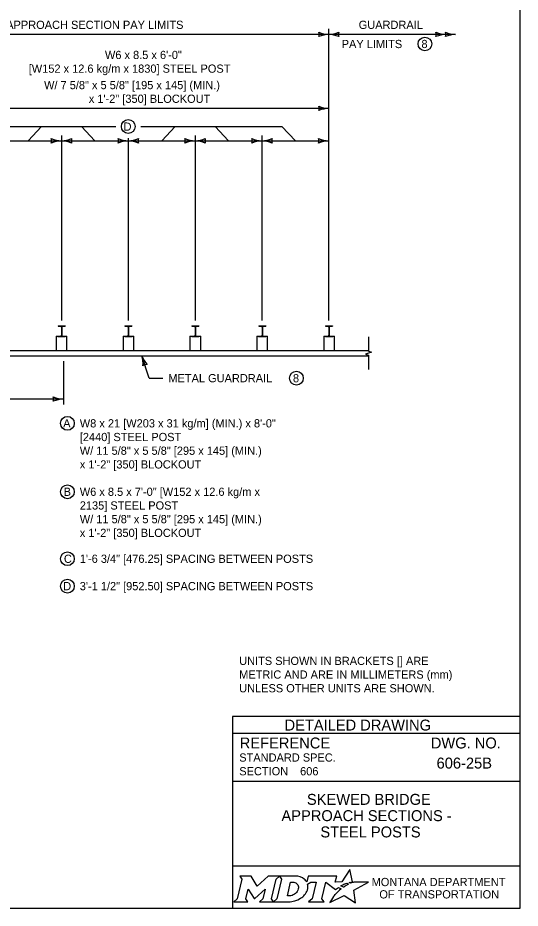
# Model space of a CAD drawing. Extents: x 49991.4 to 50021, y 49987.6 to 50011.4.
# Drawn here: x 50004.95 to 50008.61, y 50000.06 to 50006.57 of the extents above; entities that cross this region are included whole.
import ezdxf

# ---------------------------------------------------------------- set-up
doc = ezdxf.new("R2010")
doc.units = 0
for name, color, linetype in [('Level 1', 7, 'Continuous'), ('Level 2', 7, 'Continuous'), ('Level 3', 7, 'Continuous'), ('Level 6', 7, 'Continuous')]:
    doc.layers.add(name, color=color, linetype=linetype)

msp = doc.modelspace()

# ---------------------------------------------------------------- linework, layer by layer
at = {"layer": 'Level 1'}
for p, q in [((50005.2428, 50004.3152), (50005.294, 50004.3152)), ((50005.2428, 50004.3152), (50005.2428, 50004.3124)), ((50005.2428, 50004.3124), (50005.2603, 50004.3124)), ((50005.2673, 50004.3054), (50005.2673, 50004.2469)), ((50005.2695, 50004.3054), (50005.2695, 50004.2469)), ((50005.2765, 50004.3124), (50005.294, 50004.3124)), ((50005.294, 50004.3152), (50005.294, 50004.3124)), ((50005.7307, 50004.3152), (50005.782, 50004.3152)), ((50005.7307, 50004.3152), (50005.7307, 50004.3124)), ((50005.7307, 50004.3124), (50005.7483, 50004.3124)), ((50005.7552, 50004.3054), (50005.7552, 50004.2469)), ((50005.7574, 50004.3054), (50005.7574, 50004.2469)), ((50005.7644, 50004.3124), (50005.782, 50004.3124)), ((50005.782, 50004.3152), (50005.782, 50004.3124)), ((50006.2187, 50004.3152), (50006.2699, 50004.3152)), ((50006.2187, 50004.3152), (50006.2187, 50004.3124)), ((50006.2187, 50004.3124), (50006.2362, 50004.3124)), ((50006.2432, 50004.3054), (50006.2432, 50004.2469)), ((50006.2454, 50004.3054), (50006.2454, 50004.2469)), ((50006.2524, 50004.3124), (50006.2699, 50004.3124)), ((50006.2699, 50004.3152), (50006.2699, 50004.3124)), ((50006.7066, 50004.3152), (50006.7579, 50004.3152)), ((50006.7066, 50004.3152), (50006.7066, 50004.3124)), ((50006.7066, 50004.3124), (50006.7242, 50004.3124)), ((50006.7311, 50004.3054), (50006.7311, 50004.2469)), ((50006.7333, 50004.3054), (50006.7333, 50004.2469)), ((50006.7403, 50004.3124), (50006.7579, 50004.3124)), ((50006.7579, 50004.3152), (50006.7579, 50004.3124)), ((50007.1945, 50004.3152), (50007.2458, 50004.3152)), ((50007.1945, 50004.3152), (50007.1945, 50004.3124)), ((50007.1945, 50004.3124), (50007.2121, 50004.3124)), ((50007.2191, 50004.3054), (50007.2191, 50004.2469)), ((50007.2213, 50004.3054), (50007.2213, 50004.2469)), ((50007.2282, 50004.3124), (50007.2458, 50004.3124)), ((50007.2458, 50004.3152), (50007.2458, 50004.3124)), ((50005.2294, 50004.2399), (50005.2294, 50004.1359)), ((50005.2294, 50004.2399), (50005.2421, 50004.2399)), ((50005.2421, 50004.2371), (50005.2421, 50004.2399)), ((50005.2421, 50004.2371), (50005.2947, 50004.2371)), ((50005.2428, 50004.2371), (50005.2428, 50004.2399)), ((50005.2428, 50004.2399), (50005.2603, 50004.2399)), ((50005.2765, 50004.2399), (50005.294, 50004.2399)), ((50005.294, 50004.2371), (50005.294, 50004.2399)), ((50005.2947, 50004.2371), (50005.2947, 50004.2399)), ((50005.2947, 50004.2399), (50005.3074, 50004.2399)), ((50005.3074, 50004.1359), (50005.3074, 50004.2399)), ((50005.7173, 50004.2403), (50005.7173, 50004.1359)), ((50005.7173, 50004.2399), (50005.7301, 50004.2399)), ((50005.7301, 50004.2371), (50005.7301, 50004.2399)), ((50005.7301, 50004.2371), (50005.7826, 50004.2371)), ((50005.7307, 50004.2371), (50005.7307, 50004.2399)), ((50005.7307, 50004.2399), (50005.7483, 50004.2399)), ((50005.7644, 50004.2399), (50005.782, 50004.2399)), ((50005.782, 50004.2371), (50005.782, 50004.2399)), ((50005.7826, 50004.2371), (50005.7826, 50004.2399)), ((50005.7826, 50004.2399), (50005.7954, 50004.2399)), ((50005.7954, 50004.1359), (50005.7954, 50004.2399)), ((50006.2053, 50004.2399), (50006.2053, 50004.1359)), ((50006.2053, 50004.2399), (50006.218, 50004.2399)), ((50006.218, 50004.2371), (50006.218, 50004.2399)), ((50006.218, 50004.2371), (50006.2706, 50004.2371)), ((50006.2187, 50004.2371), (50006.2187, 50004.2399)), ((50006.2187, 50004.2399), (50006.2362, 50004.2399)), ((50006.2524, 50004.2399), (50006.2699, 50004.2399)), ((50006.2699, 50004.2371), (50006.2699, 50004.2399)), ((50006.2706, 50004.2371), (50006.2706, 50004.2399)), ((50006.2706, 50004.2399), (50006.2833, 50004.2399)), ((50006.2833, 50004.1359), (50006.2833, 50004.2399)), ((50006.6932, 50004.2399), (50006.6932, 50004.1359)), ((50006.6932, 50004.2399), (50006.7059, 50004.2399)), ((50006.7059, 50004.2371), (50006.7059, 50004.2399)), ((50006.7059, 50004.2371), (50006.7585, 50004.2371)), ((50006.7066, 50004.2371), (50006.7066, 50004.2399)), ((50006.7066, 50004.2399), (50006.7242, 50004.2399)), ((50006.7403, 50004.2399), (50006.7579, 50004.2399)), ((50006.7579, 50004.2371), (50006.7579, 50004.2399)), ((50006.7585, 50004.2371), (50006.7585, 50004.2399)), ((50006.7585, 50004.2399), (50006.7713, 50004.2399)), ((50006.7713, 50004.1359), (50006.7713, 50004.2399)), ((50007.1811, 50004.2399), (50007.1811, 50004.1359)), ((50007.1811, 50004.2399), (50007.1939, 50004.2399)), ((50007.1939, 50004.2371), (50007.1939, 50004.2399)), ((50007.1939, 50004.2371), (50007.2465, 50004.2371)), ((50007.1945, 50004.2371), (50007.1945, 50004.2399)), ((50007.1945, 50004.2399), (50007.2121, 50004.2399)), ((50007.2282, 50004.2399), (50007.2458, 50004.2399)), ((50007.2458, 50004.2371), (50007.2458, 50004.2399)), ((50007.2465, 50004.2371), (50007.2465, 50004.2399)), ((50007.2465, 50004.2399), (50007.2592, 50004.2399)), ((50007.2592, 50004.1359), (50007.2592, 50004.2399)), ((50003.0353, 50004.1359), (50007.507, 50004.1359)), ((50001.9767, 50004.0968), (50007.507, 50004.0968))]:
    msp.add_line(p, q, dxfattribs=at)
msp.add_lwpolyline([(50008.6146, 50011.2628), (50000.3356, 50011.2628), (50000.3356, 50000.0624), (50008.6146, 50000.0624)], close=True, dxfattribs=at)
for centre, start, end in [((50005.2603, 50004.3054), 0, 90), ((50005.2765, 50004.3054), 90, 180), ((50005.7483, 50004.3054), 0, 90), ((50005.7644, 50004.3054), 90, 180), ((50006.2362, 50004.3054), 0, 90), ((50006.2524, 50004.3054), 90, 180), ((50006.7242, 50004.3054), 0, 90), ((50006.7403, 50004.3054), 90, 180), ((50007.2121, 50004.3054), 0, 90), ((50007.2282, 50004.3054), 90, 180), ((50005.2603, 50004.2469), 270, 0), ((50005.2765, 50004.2469), 180, 270), ((50005.7483, 50004.2469), 270, 0), ((50005.7644, 50004.2469), 180, 270), ((50006.2362, 50004.2469), 270, 0), ((50006.2524, 50004.2469), 180, 270), ((50006.7242, 50004.2469), 270, 0), ((50006.7403, 50004.2469), 180, 270), ((50007.2121, 50004.2469), 270, 0), ((50007.2282, 50004.2469), 180, 270)]:
    msp.add_arc(centre, 0.00696, start, end, dxfattribs=at)
at = {"layer": 'Level 2'}
for p, q in [((50008.6146, 50001.4624), (50006.5146, 50001.4624)), ((50006.5146, 50001.4624), (50006.5146, 50000.0624)), ((50008.6146, 50001.3374), (50006.5146, 50001.3374)), ((50008.2507, 50001.1223), (50008.2507, 50001.1223)), ((50007.0089, 50001.0629), (50007.0089, 50001.0629)), ((50008.6146, 50000.9874), (50006.5146, 50000.9874)), ((50007.5646, 50000.7383), (50007.5646, 50000.7383)), ((50008.6146, 50000.3693), (50006.5146, 50000.3693))]:
    msp.add_line(p, q, dxfattribs=at)
for points in [[(50006.5701, 50000.2974), (50006.5842, 50000.274), (50006.5507, 50000.1307), (50006.525, 50000.1082), (50006.6266, 50000.1082), (50006.6131, 50000.131), (50006.6293, 50000.2011), (50006.673, 50000.1321), (50006.6783, 50000.1321), (50006.7534, 50000.2016), (50006.737, 50000.1305), (50006.7123, 50000.1085), (50006.8139, 50000.1085), (50006.8001, 50000.1318), (50006.8333, 50000.2742)], [(50006.8333, 50000.2742), (50006.8586, 50000.2974), (50006.7762, 50000.2974), (50006.6966, 50000.2244), (50006.6521, 50000.2971), (50006.5701, 50000.2974)], [(50006.9722, 50000.2974), (50006.8586, 50000.2974), (50006.8733, 50000.2745), (50006.8394, 50000.1307), (50006.8139, 50000.1085), (50006.9245, 50000.1085)], [(50007.3771, 50000.2447), (50007.3668, 50000.2503), (50007.3784, 50000.2531), (50007.39, 50000.2551), (50007.3726, 50000.3452), (50007.3131, 50000.2539), (50007.2658, 50000.2532), (50007.2761, 50000.2973), (50007.0669, 50000.2974), (50007.0568, 50000.2549), (50007.051, 50000.2632)], [(50006.9962, 50000.2107), (50006.995, 50000.2026), (50006.9918, 50000.1933), (50006.9876, 50000.1851), (50006.982, 50000.1776), (50006.9755, 50000.1707), (50006.9676, 50000.1644), (50006.9593, 50000.1597), (50006.9502, 50000.1558), (50006.9411, 50000.1535), (50006.9319, 50000.1526), (50006.916, 50000.1526), (50006.9396, 50000.2526), (50006.9556, 50000.2526), (50006.9632, 50000.252), (50006.9708, 50000.2501), (50006.9774, 50000.2471), (50006.9835, 50000.2429), (50006.9883, 50000.2379), (50006.992, 50000.2319), (50006.9947, 50000.2257), (50006.9963, 50000.2183), (50006.9963, 50000.2153), (50006.9962, 50000.2107)], [(50007.0636, 50000.2383), (50007.0882, 50000.2514), (50007.1251, 50000.2514), (50007.0965, 50000.1309), (50007.069, 50000.1082), (50007.1852, 50000.1082), (50007.1682, 50000.1311), (50007.1964, 50000.2513), (50007.2677, 50000.1996), (50007.2888, 50000.2147), (50007.3085, 50000.2038)], [(50007.2527, 50000.1479), (50007.2374, 50000.1235), (50007.2327, 50000.116), (50007.2269, 50000.1074), (50007.2246, 50000.1031), (50007.3299, 50000.1562), (50007.4138, 50000.1011), (50007.4007, 50000.1938), (50007.5076, 50000.2522), (50007.4583, 50000.253), (50007.4282, 50000.2534), (50007.4074, 50000.2537), (50007.4006, 50000.2522), (50007.3957, 50000.251), (50007.3873, 50000.2487), (50007.3771, 50000.2447)], [(50007.3267, 50000.2171), (50007.3243, 50000.2154), (50007.306, 50000.225), (50007.3163, 50000.2307), (50007.3204, 50000.2329), (50007.329, 50000.2369), (50007.3347, 50000.2395), (50007.3426, 50000.2425), (50007.3499, 50000.2452), (50007.3617, 50000.2378), (50007.3577, 50000.2357), (50007.3531, 50000.2332), (50007.3489, 50000.231), (50007.3439, 50000.2281), (50007.342, 50000.227), (50007.3393, 50000.2254), (50007.3368, 50000.224), (50007.3345, 50000.2224), (50007.3319, 50000.2206), (50007.3292, 50000.2188), (50007.3267, 50000.2171)], [(50006.9702, 50000.1158), (50006.9786, 50000.1184), (50006.9916, 50000.1238), (50007.012, 50000.1348)], [(50007.2666, 50000.164), (50007.2666, 50000.164)]]:
    msp.add_lwpolyline(points, dxfattribs=at)
for centre, radius in [((50007.9192, 50006.3745), 0.05), ((50005.755, 50005.7717), 0.0505), ((50006.9816, 50003.9337), 0.05), ((50005.3109, 50003.6039), 0.0504), ((50005.3109, 50003.1039), 0.0504), ((50005.3108, 50002.6147), 0.0504), ((50005.3108, 50002.4147), 0.0505)]:
    msp.add_circle(centre, radius, dxfattribs=at)
for centre, radius, start, end in [((50006.9953, 50000.219), 0.0709, 339.53292, 15.85821), ((50006.9513, 50000.2363), 0.1183, 300.91025, 339.13831)]:
    msp.add_arc(centre, radius, start, end, dxfattribs=at)
for centre, major_axis, ratio, start_param, end_param in [((50006.9701, 50000.25), (0.0834, -0.0037), 0.568097, 0.61298, 1.570796), ((50007.0257, 50000.2573), (0.0361, -0.0295), 0.469099, 1.225588, 1.570796), ((50007.2764, 50000.1742), (-0.0098, -0.0102), 0.016458, 3.141593, 6.279097), ((50007.2974, 50000.1941), (-0.0112, -0.0097), 0.021651, 3.157348, 6.283185), ((50006.9248, 50000.2568), (0, 0.1484), 0.987302, 3.139398, 3.456847), ((50007.2597, 50000.1559), (-0.00694, -0.00806), 0.008222, 0, 3.137361)]:
    msp.add_ellipse(centre, major_axis=major_axis, ratio=ratio, start_param=start_param, end_param=end_param, dxfattribs=at)
at = {"layer": 'Level 3'}
for p, q in [((50007.2182, 50004.3552), (50007.2182, 50006.4845)), ((50007.2182, 50006.4445), (50003.3166, 50006.4445)), ((50008.1422, 50006.4445), (50007.2182, 50006.4445)), ((50004.7798, 50005.9046), (50007.2182, 50005.9046)), ((50004.634, 50005.7717), (50005.6646, 50005.7717)), ((50005.1218, 50005.7717), (50005.0235, 50005.6672)), ((50005.4129, 50005.7717), (50005.5112, 50005.6672)), ((50005.8455, 50005.7717), (50006.8761, 50005.7717)), ((50006.0971, 50005.7717), (50005.9989, 50005.6672)), ((50006.3883, 50005.7717), (50006.4866, 50005.6672)), ((50006.8761, 50005.7717), (50006.9743, 50005.6672)), ((50005.2673, 50005.7072), (50005.2673, 50004.3552)), ((50006.2427, 50005.7072), (50006.2427, 50004.3552)), ((50006.7304, 50005.7072), (50006.7304, 50004.3552)), ((50004.7797, 50005.6672), (50005.2673, 50005.6672)), ((50005.2673, 50005.6672), (50005.755, 50005.6672)), ((50005.755, 50005.6878), (50005.755, 50004.3552)), ((50005.755, 50005.6672), (50006.2427, 50005.6672)), ((50006.2427, 50005.6672), (50006.7304, 50005.6672)), ((50006.7304, 50005.6672), (50007.2182, 50005.6672)), ((50005.9078, 50003.9337), (50005.8547, 50004.0968)), ((50005.2821, 50004.0568), (50005.2821, 50003.7411)), ((50005.9078, 50003.9337), (50006.0076, 50003.9337)), ((50005.2821, 50003.7811), (50003.3313, 50003.7811)), ((50005.2821, 50003.7811), (50005.2821, 50003.7811))]:
    msp.add_line(p, q, dxfattribs=at)
for centre, radius, start, end in [((50007.2269, 50006.6556), 0.2113, 247.45601, 267.63952), ((50007.0964, 50006.4445), 0.0521, 342.13882, 17.86118), ((50007.2291, 50006.2234), 0.2214, 92.82731, 112.07716), ((50007.2073, 50006.6657), 0.2214, 272.82731, 292.07716), ((50007.2095, 50006.2334), 0.2113, 67.45601, 87.63952), ((50007.34, 50006.4445), 0.0521, 162.13882, 197.86118), ((50008.0811, 50006.6556), 0.2113, 247.45601, 267.63952), ((50007.9506, 50006.4445), 0.0521, 342.13882, 17.86118), ((50008.0834, 50006.2234), 0.2214, 92.82731, 112.07716), ((50008.1509, 50006.6556), 0.2113, 247.45601, 267.63952), ((50008.0204, 50006.4445), 0.0521, 342.13882, 17.86118), ((50008.1531, 50006.2234), 0.2214, 92.82731, 112.07716), ((50007.2269, 50006.1157), 0.2113, 247.45601, 267.63952), ((50007.0964, 50005.9046), 0.0521, 342.13882, 17.86118), ((50007.2291, 50005.6834), 0.2214, 92.82731, 112.07716), ((50005.2763, 50005.8839), 0.2168, 247.45601, 267.63952), ((50005.1423, 50005.6672), 0.0534, 342.13882, 17.86118), ((50005.2786, 50005.4403), 0.2273, 92.82731, 112.07716), ((50005.2561, 50005.8942), 0.2273, 272.82731, 292.07716), ((50005.2584, 50005.4506), 0.2168, 67.45601, 87.63952), ((50005.3924, 50005.6672), 0.0534, 162.13882, 197.86118), ((50005.764, 50005.8839), 0.2168, 247.45601, 267.63952), ((50005.63, 50005.6672), 0.0534, 342.13882, 17.86118), ((50005.7662, 50005.4403), 0.2273, 92.82731, 112.07716), ((50005.7438, 50005.8942), 0.2273, 272.82731, 292.07716), ((50005.7461, 50005.4506), 0.2168, 67.45601, 87.63952), ((50005.8801, 50005.6672), 0.0534, 162.13882, 197.86118), ((50006.2516, 50005.8839), 0.2168, 247.45601, 267.63952), ((50006.1177, 50005.6672), 0.0534, 342.13882, 17.86118), ((50006.2539, 50005.4403), 0.2273, 92.82731, 112.07716), ((50006.2315, 50005.8942), 0.2273, 272.82731, 292.07716), ((50006.2338, 50005.4506), 0.2168, 67.45601, 87.63952), ((50006.3678, 50005.6672), 0.0534, 162.13882, 197.86118), ((50006.7393, 50005.8839), 0.2168, 247.45601, 267.63952), ((50006.6053, 50005.6672), 0.0534, 342.13882, 17.86118), ((50006.7416, 50005.4403), 0.2273, 92.82731, 112.07716), ((50006.7192, 50005.8942), 0.2273, 272.82731, 292.07716), ((50006.7215, 50005.4506), 0.2168, 67.45601, 87.63952), ((50006.8555, 50005.6672), 0.0534, 162.13882, 197.86118), ((50007.2271, 50005.8839), 0.2168, 247.45601, 267.63952), ((50007.0931, 50005.6672), 0.0534, 342.13882, 17.86118), ((50007.2294, 50005.4403), 0.2273, 92.82731, 112.07716), ((50005.6513, 50004.0398), 0.2113, 355.47646, 15.65997), ((50006.0616, 50004.1756), 0.2214, 200.84776, 220.09761), ((50005.8924, 50003.981), 0.0521, 90.15927, 125.88163), ((50005.291, 50003.9978), 0.2168, 247.45601, 267.63952), ((50005.157, 50003.7811), 0.0534, 342.13882, 17.86118), ((50005.2933, 50003.5541), 0.2273, 92.82731, 112.07716)]:
    msp.add_arc(centre, radius, start, end, dxfattribs=at)
at = {"layer": 'Level 6'}
for p, q in [((50007.507, 50004.2359), (50007.507, 50004.1317)), ((50007.5286, 50004.124), (50007.4853, 50004.1086)), ((50007.4853, 50004.1086), (50007.507, 50004.1009)), ((50007.507, 50004.1317), (50007.5286, 50004.124)), ((50007.507, 50004.1009), (50007.507, 50003.9968))]:
    msp.add_line(p, q, dxfattribs=at)

# ---------------------------------------------------------------- texts
at = {"layer": 'Level 2'}
for s, height, p in [('25\'-0" [7.62 m] BRIDGE APPROACH SECTION PAY LIMITS', 0.06, (50003.9958, 50006.4845)), ('GUARDRAIL', 0.06, (50007.4365, 50006.4845)), ('PAY LIMITS', 0.06, (50007.3123, 50006.3445)), ('8', 0.06, (50007.8942, 50006.3445)), ('W6 x 8.5 x 6\'-0"', 0.06, (50005.5849, 50006.2645)), (' [W152 x 12.6 kg/m x 1830] STEEL POST', 0.06, (50005.0066, 50006.1645)), ('W/ 7 5/8" x 5 5/8" [195 x 145] (MIN.)', 0.06, (50005.1407, 50006.0445)), (' x 1\'-2" [350] BLOCKOUT', 0.06, (50005.4448, 50005.9445)), ('D', 0.06, (50005.7206, 50005.7411)), ('METAL GUARDRAIL', 0.06, (50006.0476, 50003.9037)), ('8', 0.06, (50006.9566, 50003.9037)), ('A', 0.06, (50005.2802, 50003.5739)), ('W8 x 21 [W203 x 31 kg/m] (MIN.) x 8\'-0" ', 0.06, (50005.4013, 50003.5739)), ('[2440] STEEL POST', 0.06, (50005.4013, 50003.4739)), ('W/ 11 5/8" x 5 5/8" [295 x 145] (MIN.) ', 0.06, (50005.4013, 50003.3739)), ('x 1\'-2" [350] BLOCKOUT', 0.06, (50005.4013, 50003.2739)), ('B', 0.06, (50005.2832, 50003.0739)), ('W6 x 8.5 x 7\'-0" [W152 x 12.6 kg/m x ', 0.06, (50005.4013, 50003.0739)), ('2135] STEEL POST', 0.06, (50005.4013, 50002.9739)), ('W/ 11 5/8" x 5 5/8" [295 x 145] (MIN.) ', 0.06, (50005.4013, 50002.8739)), ('x 1\'-2" [350] BLOCKOUT', 0.06, (50005.4013, 50002.7739)), ('C', 0.06, (50005.2853, 50002.5846)), ('1\'-6 3/4" [476.25] SPACING BETWEEN POSTS', 0.06, (50005.4013, 50002.5847)), ('D', 0.06, (50005.2805, 50002.3847)), ('3\'-1 1/2" [952.50] SPACING BETWEEN POSTS', 0.06, (50005.4013, 50002.3847)), ('UNITS SHOWN IN BRACKETS [] ARE ', 0.06, (50006.5642, 50001.8389)), ('METRIC AND ARE IN MILLIMETERS (mm) ', 0.06, (50006.5642, 50001.7389)), ('UNLESS OTHER UNITS ARE SHOWN.', 0.06, (50006.5642, 50001.6389)), ('DETAILED DRAWING', 0.0799, (50006.8956, 50001.3599)), ('REFERENCE', 0.08, (50006.5682, 50001.229)), ('DWG. NO.', 0.08, (50007.9624, 50001.229)), ('STANDARD SPEC.', 0.06, (50006.5649, 50001.133)), ('606-25B', 0.08, (50008.0047, 50001.0823)), ('SECTION', 0.06, (50006.5649, 50001.033)), ('606', 0.06, (50007.0089, 50001.0329)), ('SKEWED BRIDGE ', 0.08, (50007.0586, 50000.8173)), ('APPROACH SECTIONS -', 0.08, (50006.8728, 50000.6983)), ('STEEL POSTS', 0.08, (50007.1569, 50000.5793)), ('MONTANA DEPARTMENT', 0.06, (50007.5308, 50000.2236)), ('OF TRANSPORTATION', 0.06, (50007.587, 50000.1336))]:
    msp.add_text(s, height=height, dxfattribs=at).set_placement(p)

doc.saveas('drawing.dxf')
